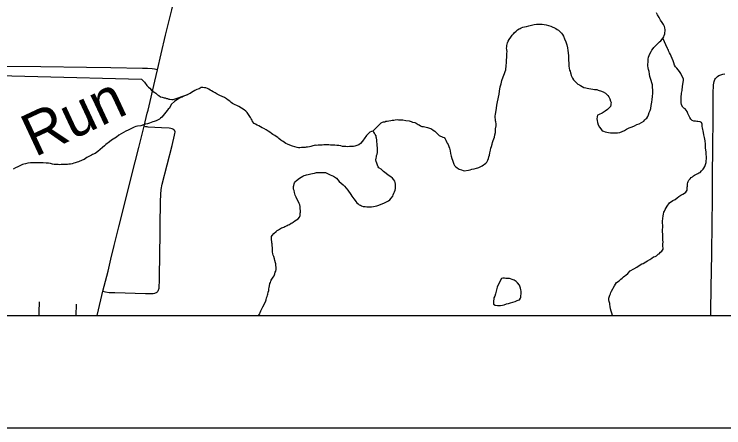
# Model space of a CAD drawing. Extents: x 2.1 to 73.9, y 4 to 26.
# Drawn here: x 43.39 to 44.021, y 18.005 to 18.373 of the extents above; entities that cross this region are included whole.
import ezdxf

# ---------------------------------------------------------------- set-up
doc = ezdxf.new("R2010")
doc.units = 0
for name, color, linetype in [('GM_X_City_Street', 7, 'Continuous'), ('GM_X_County_Road', 7, 'Continuous'), ('GM_X_Minor_Lake', 7, 'Continuous'), ('GM_X_Minor_Lake_Text', 7, 'Continuous'), ('GM_X_Minor_River', 7, 'Continuous'), ('GM_X_Township_Road', 7, 'Continuous'), ('SH_Data', 7, 'Continuous')]:
    doc.layers.add(name, color=color, linetype=linetype)

msp = doc.modelspace()

# ---------------------------------------------------------------- linework, layer by layer
at = {"layer": 'GM_X_City_Street'}
msp.add_line((43.44493, 18.10511), (43.44524, 18.11503), dxfattribs=at)
for points in [[(43.4688, 18.1266), (43.47103, 18.12599), (43.47421, 18.12555), (43.47923, 18.12547), (43.50655, 18.12466), (43.50867, 18.12459), (43.51332, 18.12468), (43.51486, 18.12486), (43.51566, 18.1251), (43.51632, 18.12542), (43.51689, 18.12584), (43.51743, 18.12647), (43.51783, 18.12703), (43.5182, 18.12781), (43.51844, 18.12849), (43.51864, 18.12929), (43.51883, 18.13083), (43.519, 18.13548), (43.51919, 18.14784), (43.51922, 18.15093), (43.5197, 18.18643), (43.51978, 18.19259), (43.51988, 18.19878), (43.52002, 18.20653), (43.52019, 18.21273), (43.52064, 18.21735), (43.52145, 18.22192), (43.5302, 18.25649), (43.53237, 18.26552), (43.53271, 18.26699), (43.53287, 18.26812), (43.5329, 18.26844), (43.53289, 18.26875), (43.53277, 18.26926), (43.5326, 18.2696), (43.53238, 18.26984), (43.53177, 18.27039), (43.53105, 18.27081), (43.53047, 18.27108), (43.52906, 18.27154), (43.52758, 18.2718), (43.52083, 18.27218), (43.50896, 18.27272), (43.50808, 18.27283), (43.50699, 18.27302), (43.50535, 18.27346)], [(43.41201, 18.10511), (43.41207, 18.108), (43.41237, 18.11723)]]:
    msp.add_lwpolyline(points, dxfattribs=at)
at = {"layer": 'GM_X_County_Road'}
for points in [[(43.51734, 18.32372), (43.52065, 18.33781), (43.52449, 18.35446), (43.52991, 18.37713), (43.53608, 18.40442), (43.5417, 18.42863), (43.54558, 18.44528), (43.54639, 18.44885)], [(43.50535, 18.27346), (43.50815, 18.28503), (43.50885, 18.2879), (43.51497, 18.3136), (43.51734, 18.32372)], [(44.01442, 18.31698), (44.01549, 18.31775), (44.01663, 18.31851), (44.01832, 18.31928), (44.0203, 18.31986), (44.02187, 18.3202)], [(44.00955, 18.10511), (44.00957, 18.1085), (44.00995, 18.13023), (44.01028, 18.15972), (44.01067, 18.18765), (44.01095, 18.20782), (44.01111, 18.228), (44.01143, 18.25594), (44.01162, 18.27922), (44.0117, 18.29318), (44.01173, 18.30406), (44.01182, 18.30879), (44.01197, 18.31048), (44.01251, 18.31346), (44.01319, 18.31507), (44.0138, 18.31607), (44.01442, 18.31698)], [(43.4688, 18.1266), (43.46988, 18.13108), (43.47331, 18.14463), (43.47588, 18.15519), (43.47887, 18.16725), (43.48297, 18.18385), (43.48712, 18.20042), (43.49427, 18.22907), (43.50069, 18.2547), (43.50535, 18.27346)], [(43.46367, 18.10511), (43.46695, 18.11901), (43.4688, 18.1266)]]:
    msp.add_lwpolyline(points, dxfattribs=at)
at = {"layer": 'GM_X_Minor_Lake'}
for points in [[(43.82344, 18.13806), (43.81971, 18.13126), (43.81931, 18.13032), (43.81887, 18.12786), (43.81804, 18.12446), (43.81723, 18.1222), (43.81663, 18.12089), (43.81641, 18.11956), (43.81618, 18.11805), (43.81613, 18.11596), (43.81611, 18.11501), (43.81781, 18.11421), (43.8197, 18.11398), (43.82122, 18.11394), (43.82256, 18.1141), (43.82408, 18.11426), (43.8258, 18.1146), (43.82772, 18.11531), (43.82963, 18.11584), (43.83135, 18.11637), (43.83537, 18.11761), (43.83729, 18.11832), (43.83825, 18.11868), (43.83921, 18.11904), (43.84019, 18.12035), (43.8404, 18.12148), (43.84063, 18.123), (43.84084, 18.12394), (43.84087, 18.12527), (43.84071, 18.12679), (43.84036, 18.12794), (43.8402, 18.12927), (43.84003, 18.13023), (43.83931, 18.13214), (43.83765, 18.13427), (43.83634, 18.13544), (43.83466, 18.13662), (43.83277, 18.13723), (43.83126, 18.13765), (43.83031, 18.13786), (43.82936, 18.13788), (43.82842, 18.13809), (43.82728, 18.13812), (43.82595, 18.13815), (43.82443, 18.13818), (43.82344, 18.13806)], [(43.82344, 18.13806), (43.81971, 18.13126), (43.81931, 18.13032), (43.81887, 18.12786), (43.81804, 18.12446), (43.81723, 18.1222), (43.81663, 18.12089), (43.81641, 18.11956), (43.81618, 18.11805), (43.81613, 18.11596), (43.81611, 18.11501), (43.81781, 18.11421), (43.8197, 18.11398), (43.82122, 18.11394), (43.82256, 18.1141), (43.82408, 18.11426), (43.8258, 18.1146), (43.82772, 18.11531), (43.82963, 18.11584), (43.83135, 18.11637), (43.83537, 18.11761), (43.83729, 18.11832), (43.83825, 18.11868)], [(43.83825, 18.11868), (43.83921, 18.11904), (43.84019, 18.12035), (43.8404, 18.12148), (43.84063, 18.123), (43.84084, 18.12394), (43.84087, 18.12527), (43.84071, 18.12679), (43.84036, 18.12794), (43.8402, 18.12927), (43.84003, 18.13023), (43.83931, 18.13214), (43.83765, 18.13427), (43.83634, 18.13544), (43.83466, 18.13662), (43.83277, 18.13723), (43.83126, 18.13765), (43.83031, 18.13786), (43.82936, 18.13788), (43.82842, 18.13809), (43.82728, 18.13812), (43.82595, 18.13815), (43.82443, 18.13818), (43.82344, 18.13806)]]:
    msp.add_lwpolyline(points, dxfattribs=at)
at = {"layer": 'GM_X_Minor_River'}
for points in [[(43.96733, 18.36399), (43.96624, 18.36591), (43.96476, 18.36803), (43.96348, 18.37034), (43.96202, 18.37266), (43.96111, 18.37457)], [(43.81807, 18.27831), (43.81791, 18.27945), (43.81776, 18.28117), (43.81779, 18.28287), (43.81801, 18.28401), (43.81824, 18.2859), (43.81847, 18.28761), (43.81871, 18.28969), (43.81914, 18.29215), (43.81979, 18.29536), (43.82127, 18.30198), (43.82152, 18.30482), (43.82218, 18.30861), (43.82299, 18.31125), (43.82363, 18.31427), (43.82485, 18.31747), (43.82586, 18.3203), (43.82666, 18.32218), (43.82708, 18.32369), (43.8273, 18.32501), (43.82752, 18.32634), (43.82755, 18.32786), (43.82778, 18.32975), (43.82783, 18.33165), (43.82785, 18.33279), (43.82808, 18.3343), (43.82811, 18.33582), (43.82814, 18.33734), (43.82817, 18.33848), (43.8282, 18.33962), (43.82805, 18.34171), (43.82789, 18.34304), (43.82792, 18.34418), (43.82813, 18.34532), (43.82835, 18.34664), (43.82876, 18.34758), (43.82917, 18.34909), (43.83016, 18.35078), (43.83153, 18.35284), (43.83271, 18.35452), (43.83388, 18.35563), (43.83466, 18.35675), (43.83622, 18.35824), (43.83757, 18.35916), (43.83892, 18.36007), (43.83989, 18.36062), (43.84085, 18.36117), (43.84219, 18.36171), (43.84372, 18.36205), (43.84544, 18.3624), (43.84754, 18.36292), (43.85002, 18.36343), (43.85232, 18.36395), (43.85442, 18.36428), (43.85708, 18.36441), (43.85936, 18.36436), (43.86126, 18.36412), (43.86296, 18.36371), (43.86523, 18.36327), (43.86711, 18.36247), (43.87163, 18.36047), (43.87294, 18.35968), (43.87388, 18.35909), (43.875, 18.35811), (43.87667, 18.35636), (43.8776, 18.3552), (43.87851, 18.35366), (43.87941, 18.35136), (43.88049, 18.34868), (43.88138, 18.346), (43.88189, 18.34333), (43.88241, 18.34085), (43.88274, 18.33875), (43.88287, 18.33628), (43.88301, 18.334), (43.88296, 18.33191), (43.88311, 18.33001), (43.88308, 18.32849), (43.88323, 18.32697), (43.88357, 18.32506), (43.88372, 18.32335), (43.88427, 18.32238), (43.88462, 18.32105), (43.88498, 18.32009), (43.88533, 18.31875), (43.88587, 18.31741), (43.8866, 18.31625), (43.88734, 18.31491), (43.88844, 18.31355), (43.88994, 18.31219), (43.89124, 18.31102), (43.89255, 18.31023), (43.89368, 18.30963), (43.89499, 18.30884), (43.8965, 18.30805), (43.89839, 18.30763), (43.89952, 18.30741), (43.90104, 18.307), (43.90274, 18.30677), (43.90464, 18.30653), (43.90615, 18.30631)], [(43.90615, 18.30631), (43.90729, 18.30628), (43.90824, 18.30607), (43.90918, 18.30567), (43.91032, 18.30545), (43.91145, 18.30505), (43.91371, 18.30424), (43.91596, 18.30286), (43.91801, 18.30091), (43.91893, 18.29956), (43.91965, 18.29783), (43.92018, 18.29592), (43.92072, 18.29477), (43.92069, 18.29344), (43.92067, 18.29249), (43.92026, 18.29117), (43.9189, 18.28968), (43.91754, 18.28839), (43.91541, 18.28691), (43.91271, 18.28527), (43.91021, 18.28399), (43.90868, 18.28346), (43.90826, 18.28176), (43.90823, 18.28024), (43.90838, 18.27853), (43.90872, 18.27681), (43.90925, 18.2749), (43.91034, 18.27278), (43.91163, 18.27105), (43.91293, 18.2695), (43.91406, 18.26909), (43.91538, 18.26849), (43.91689, 18.26827), (43.9186, 18.26785), (43.9203, 18.26762), (43.9222, 18.26758), (43.92429, 18.26753), (43.92639, 18.26767), (43.92867, 18.268), (43.93059, 18.26871), (43.9327, 18.26962), (43.93463, 18.2709), (43.93694, 18.27218), (43.93943, 18.27307), (43.94174, 18.27397), (43.94366, 18.27506), (43.94577, 18.27578), (43.94982, 18.27815), (43.95079, 18.27908), (43.95157, 18.2802), (43.95273, 18.28075), (43.95351, 18.28206), (43.95412, 18.28356), (43.95474, 18.28583), (43.95554, 18.28752), (43.95615, 18.2894), (43.95659, 18.29205), (43.95704, 18.29489), (43.95728, 18.29736), (43.95753, 18.30001), (43.95778, 18.30285), (43.95782, 18.30456), (43.95786, 18.30627), (43.95771, 18.30779), (43.95773, 18.30893), (43.95757, 18.31027), (43.95704, 18.31218), (43.95633, 18.31409), (43.9558, 18.316), (43.95527, 18.31773), (43.95493, 18.31982), (43.95461, 18.32211), (43.95408, 18.32402), (43.95373, 18.32555), (43.95358, 18.32726), (43.95362, 18.32878), (43.95365, 18.33049), (43.95368, 18.33182), (43.9539, 18.33314), (43.95414, 18.33504), (43.95474, 18.33654), (43.95534, 18.33805), (43.95634, 18.33993), (43.95713, 18.34124), (43.95811, 18.34254), (43.95889, 18.34366), (43.95987, 18.34478), (43.96084, 18.34571), (43.96259, 18.34757), (43.96376, 18.34868), (43.96492, 18.34961), (43.96628, 18.35109), (43.96766, 18.35315), (43.96807, 18.35428), (43.96848, 18.35579), (43.9687, 18.35693), (43.96892, 18.35825), (43.96875, 18.3594), (43.9686, 18.36111), (43.96825, 18.36226), (43.96733, 18.36399)], [(43.98886, 18.22237), (43.98908, 18.22351), (43.98948, 18.22445), (43.99008, 18.22557), (43.99124, 18.22669), (43.99203, 18.22781), (43.99318, 18.22854), (43.99415, 18.22928), (43.99512, 18.22983), (43.99627, 18.23056), (43.998, 18.23147), (43.99897, 18.23202), (43.99992, 18.23238), (44.00129, 18.23368), (44.00265, 18.23516), (44.00343, 18.23628), (44.00404, 18.23779), (44.00484, 18.23948), (44.00526, 18.24118), (44.00548, 18.2427), (44.00571, 18.2444), (44.00528, 18.25049), (44.00479, 18.2543), (44.00467, 18.25753), (44.00436, 18.26058), (44.00386, 18.26344), (44.00334, 18.26592), (44.003, 18.26782), (44.00266, 18.26935), (44.00231, 18.27069), (44.00215, 18.27202), (44.00179, 18.27317), (44.00182, 18.27431), (44.00184, 18.27545), (44.00111, 18.2768), (43.99999, 18.27739), (43.99809, 18.27762), (43.99696, 18.27784), (43.99582, 18.27787), (43.99449, 18.27809), (43.99298, 18.27869), (43.99168, 18.27986), (43.99095, 18.28121), (43.99003, 18.28294), (43.98913, 18.28486), (43.98841, 18.28658), (43.98749, 18.28793), (43.98656, 18.2889), (43.98562, 18.28968), (43.98469, 18.29046), (43.98341, 18.29258), (43.98307, 18.29449), (43.98311, 18.2962), (43.98316, 18.29829), (43.9832, 18.30019), (43.98342, 18.3017), (43.98345, 18.30303), (43.98367, 18.30416), (43.98388, 18.3053), (43.9841, 18.30662), (43.98432, 18.30795), (43.98435, 18.30909), (43.98457, 18.3106), (43.985, 18.31268), (43.98523, 18.3142), (43.98506, 18.31534), (43.9829, 18.32052), (43.98179, 18.32225), (43.9805, 18.3238), (43.9792, 18.32516), (43.97809, 18.32651), (43.97717, 18.32786), (43.97664, 18.32996), (43.97592, 18.33169), (43.97521, 18.3338), (43.9743, 18.33572), (43.97358, 18.33744), (43.97285, 18.33879), (43.97212, 18.33995), (43.97176, 18.34109), (43.97121, 18.34205), (43.97085, 18.34263), (43.96676, 18.3518)], [(43.01674, 18.33636), (43.31889, 18.33107), (43.31846, 18.32025), (43.50294, 18.31531)], [(43.50294, 18.31531), (43.50573, 18.31259), (43.50776, 18.3097), (43.50925, 18.30833), (43.51037, 18.30736), (43.51167, 18.306), (43.51353, 18.30444), (43.51484, 18.30346), (43.51578, 18.30287), (43.51727, 18.3015), (43.5184, 18.30091), (43.52008, 18.29973), (43.52141, 18.29951), (43.5231, 18.2989), (43.52424, 18.29869), (43.52537, 18.29828), (43.52632, 18.29807), (43.52745, 18.29766), (43.52839, 18.29745), (43.52991, 18.29742), (43.53124, 18.29739), (43.54427, 18.30165)], [(43.69476, 18.25624), (43.69285, 18.25572), (43.69152, 18.25556), (43.6898, 18.25541), (43.68809, 18.25545), (43.68638, 18.2553), (43.68486, 18.25533), (43.68296, 18.25537), (43.68182, 18.25559), (43.68031, 18.256), (43.6786, 18.25623), (43.6769, 18.25646), (43.675, 18.2567), (43.6731, 18.25674), (43.6712, 18.25678), (43.66968, 18.25682), (43.66835, 18.25685), (43.6674, 18.25687), (43.66645, 18.25689), (43.66531, 18.25692), (43.66379, 18.25676), (43.66189, 18.2568), (43.66017, 18.25665), (43.65846, 18.2565), (43.65751, 18.25652), (43.65655, 18.25636), (43.6556, 18.256), (43.65368, 18.25547), (43.65253, 18.25512), (43.65082, 18.25497), (43.64968, 18.2548), (43.64853, 18.25464), (43.64701, 18.25448), (43.64549, 18.25452), (43.64396, 18.25436), (43.64263, 18.25439), (43.6415, 18.25461), (43.63734, 18.25585), (43.63489, 18.25666), (43.63301, 18.25746), (43.6315, 18.25826), (43.63019, 18.25905), (43.62907, 18.25983), (43.62794, 18.26043), (43.627, 18.26102), (43.62514, 18.26258), (43.6242, 18.26336), (43.62289, 18.26434), (43.62159, 18.26532), (43.61989, 18.26612), (43.61877, 18.2669), (43.61728, 18.26808), (43.61559, 18.26926), (43.61391, 18.27043), (43.61203, 18.27143), (43.61033, 18.27223), (43.60883, 18.27302), (43.60733, 18.27381), (43.60582, 18.27442), (43.60451, 18.27521), (43.60319, 18.276), (43.6019, 18.27773), (43.60136, 18.27889), (43.60063, 18.28023), (43.59989, 18.2812), (43.59934, 18.28216), (43.59824, 18.2839), (43.59714, 18.28582), (43.59584, 18.28699), (43.59453, 18.28797), (43.58966, 18.29112), (43.58796, 18.29192), (43.58646, 18.29252), (43.58533, 18.29312), (43.58401, 18.29372), (43.5827, 18.29451), (43.58158, 18.29567), (43.58009, 18.29684), (43.57859, 18.29783), (43.57691, 18.29901), (43.57484, 18.3), (43.57277, 18.301), (43.57051, 18.30219), (43.56864, 18.30318), (43.56695, 18.30417), (43.56544, 18.30496), (43.56413, 18.30575), (43.56301, 18.30654), (43.56169, 18.30695), (43.56037, 18.30755), (43.55923, 18.30777), (43.55753, 18.30799), (43.556, 18.30784), (43.55427, 18.30693), (43.55216, 18.30622), (43.55062, 18.3053), (43.54908, 18.30439), (43.54754, 18.30347), (43.54638, 18.30274), (43.54542, 18.30238), (43.54427, 18.30165)], [(43.54427, 18.30165), (43.54273, 18.30111), (43.54023, 18.29984), (43.53909, 18.29949), (43.53793, 18.29894), (43.53697, 18.29859), (43.53523, 18.2973), (43.53369, 18.29638), (43.53234, 18.29546), (43.52982, 18.29305), (43.52863, 18.29099), (43.52784, 18.28968), (43.52686, 18.28856), (43.52589, 18.28744), (43.52472, 18.28614), (43.52354, 18.28446), (43.52236, 18.28296), (43.52119, 18.28166), (43.52003, 18.28055), (43.51906, 18.27981), (43.51791, 18.27908), (43.51618, 18.27836), (43.51445, 18.27764), (43.51311, 18.27729), (43.51158, 18.27675), (43.51005, 18.27622), (43.50832, 18.27569), (43.5066, 18.27534), (43.50469, 18.27482), (43.50239, 18.27392), (43.49953, 18.27361), (43.498, 18.27326), (43.49647, 18.27254), (43.49474, 18.27182), (43.49301, 18.27091), (43.49109, 18.27), (43.48916, 18.26909), (43.48704, 18.26781), (43.48493, 18.26672), (43.483, 18.26544), (43.48087, 18.26377), (43.47779, 18.26195), (43.47644, 18.26122), (43.4747, 18.25974), (43.47353, 18.25881), (43.47257, 18.25807), (43.47141, 18.25734), (43.47024, 18.25604), (43.4685, 18.25456), (43.46636, 18.25271), (43.46423, 18.25105), (43.46191, 18.2492), (43.45961, 18.2483), (43.45846, 18.24776), (43.45442, 18.24557), (43.45325, 18.24465), (43.45191, 18.24392), (43.45037, 18.24338), (43.44922, 18.24284), (43.44807, 18.2423), (43.44711, 18.24194), (43.44577, 18.2414), (43.44405, 18.24106), (43.4429, 18.24052), (43.44137, 18.24017), (43.43984, 18.23982), (43.4385, 18.23966), (43.43736, 18.2395), (43.43641, 18.23952), (43.43546, 18.23954), (43.43432, 18.23938), (43.4328, 18.23941), (43.43147, 18.23945), (43.43013, 18.23928), (43.4288, 18.23932), (43.42785, 18.23934), (43.42671, 18.23936), (43.42539, 18.23958), (43.42387, 18.23981), (43.42217, 18.24042), (43.42028, 18.24065), (43.41819, 18.2407), (43.41572, 18.24094), (43.41401, 18.24079), (43.4123, 18.24083), (43.41078, 18.24086), (43.40925, 18.2409), (43.40698, 18.24095), (43.40431, 18.24082), (43.40183, 18.2405), (43.39992, 18.24016), (43.39839, 18.23981), (43.39725, 18.23946), (43.39551, 18.23855), (43.39302, 18.23747), (43.3909, 18.23638), (43.38879, 18.23528)], [(43.70877, 18.269), (43.71613, 18.27646), (43.71747, 18.277), (43.71843, 18.27736), (43.71939, 18.27752), (43.72054, 18.27788), (43.72168, 18.27804), (43.72302, 18.27839), (43.72493, 18.27873), (43.72607, 18.27889), (43.72741, 18.27905), (43.72874, 18.27921), (43.73046, 18.27936), (43.73178, 18.27933), (43.7333, 18.27911), (43.73539, 18.27906), (43.73823, 18.27861), (43.74107, 18.27817), (43.74297, 18.27775), (43.74428, 18.27714), (43.74617, 18.27672), (43.74731, 18.27632), (43.74824, 18.27573), (43.74918, 18.27513), (43.75012, 18.27473), (43.75125, 18.27395), (43.75256, 18.27335), (43.75389, 18.27313), (43.75749, 18.27248), (43.75918, 18.27187), (43.76012, 18.27146), (43.76107, 18.27106), (43.76238, 18.27009), (43.76387, 18.2691), (43.765, 18.26832), (43.76648, 18.26676), (43.76778, 18.26521), (43.76891, 18.26481), (43.76985, 18.26441), (43.77117, 18.26381), (43.7723, 18.2634), (43.77323, 18.26243), (43.77377, 18.26109), (43.7745, 18.25955), (43.77504, 18.2584), (43.77577, 18.25724), (43.77613, 18.25628), (43.77649, 18.25533), (43.77703, 18.25399), (43.77739, 18.25284), (43.77774, 18.2515), (43.77807, 18.24921), (43.77858, 18.24673), (43.77911, 18.24482), (43.77964, 18.24329), (43.78, 18.24233), (43.78053, 18.24061), (43.78089, 18.23965), (43.78163, 18.23869), (43.78274, 18.23733), (43.78386, 18.23636), (43.78574, 18.23536), (43.78762, 18.23456), (43.78913, 18.23415), (43.79008, 18.23393), (43.79408, 18.23441), (43.79542, 18.23476), (43.79695, 18.2353), (43.79886, 18.23563), (43.80097, 18.23615), (43.8023, 18.2365), (43.80326, 18.23686), (43.80442, 18.23741), (43.80596, 18.23832), (43.8073, 18.23905), (43.80827, 18.2396), (43.80924, 18.24052), (43.81021, 18.24145), (43.81101, 18.24333), (43.81161, 18.24465), (43.81203, 18.24635), (43.81264, 18.24785), (43.81306, 18.24993), (43.81349, 18.2522), (43.81392, 18.25409), (43.81433, 18.2556), (43.81494, 18.25749), (43.81536, 18.259), (43.81597, 18.26069), (43.81657, 18.2622), (43.81699, 18.2639), (43.81742, 18.26598), (43.81784, 18.26806), (43.8181, 18.27109), (43.81854, 18.27374), (43.81858, 18.27564), (43.81824, 18.27736), (43.81807, 18.27831)], [(43.65695, 18.23185), (43.65867, 18.23219), (43.66058, 18.23233), (43.66229, 18.23229), (43.664, 18.23245), (43.66552, 18.23241), (43.66685, 18.23219), (43.66779, 18.23179), (43.6691, 18.231), (43.6708, 18.2302), (43.6723, 18.2296), (43.67381, 18.22899), (43.67475, 18.22859), (43.67643, 18.22722), (43.67773, 18.22586), (43.67903, 18.22431), (43.6807, 18.22276), (43.68238, 18.22139), (43.6835, 18.22022), (43.68517, 18.21829), (43.68646, 18.21674), (43.68941, 18.21268), (43.69014, 18.21134), (43.69106, 18.20999), (43.69199, 18.20882), (43.6931, 18.20747), (43.69384, 18.2065), (43.69476, 18.20534), (43.69588, 18.20456), (43.69681, 18.20359), (43.69775, 18.20318), (43.69889, 18.20278), (43.70039, 18.20218), (43.70191, 18.20195), (43.70361, 18.20172), (43.70495, 18.20188), (43.70628, 18.20185), (43.7078, 18.20182), (43.70933, 18.20216), (43.71104, 18.20231), (43.71238, 18.20266), (43.71429, 18.20319), (43.71622, 18.20409), (43.71852, 18.20518), (43.72044, 18.2059), (43.72159, 18.20644), (43.72274, 18.20698), (43.7241, 18.2079), (43.72508, 18.2094), (43.72664, 18.21126), (43.72705, 18.21258), (43.72765, 18.2139), (43.72806, 18.21503), (43.72867, 18.21672), (43.72889, 18.21805), (43.72891, 18.219), (43.72893, 18.22014), (43.72897, 18.22184), (43.72882, 18.22337), (43.72846, 18.22452), (43.72754, 18.22587), (43.72625, 18.22742), (43.72494, 18.22839), (43.72325, 18.22938), (43.7182, 18.23311), (43.71635, 18.23524), (43.71428, 18.23643), (43.71354, 18.23739), (43.71301, 18.23892), (43.71228, 18.24065), (43.71174, 18.24199), (43.71159, 18.24351), (43.71181, 18.24503), (43.71203, 18.24635), (43.71225, 18.24749), (43.71265, 18.24862), (43.71307, 18.25013), (43.71309, 18.25108), (43.71312, 18.25241), (43.71298, 18.2545), (43.71282, 18.25621), (43.71267, 18.25773), (43.71252, 18.25964), (43.71237, 18.26154), (43.71202, 18.26288), (43.71186, 18.26383), (43.71169, 18.26497), (43.71096, 18.26613), (43.71041, 18.26728), (43.70967, 18.26825), (43.70874, 18.26903), (43.7076, 18.26887), (43.70625, 18.26814), (43.70489, 18.26703), (43.70333, 18.26517), (43.70118, 18.26237), (43.70039, 18.26124), (43.6996, 18.26012), (43.69785, 18.25826), (43.6963, 18.25697), (43.69476, 18.25624)], [(43.60933, 18.1091), (43.61013, 18.11098), (43.61112, 18.11267), (43.61332, 18.11736), (43.61392, 18.11887), (43.61434, 18.12076), (43.61475, 18.12208), (43.61516, 18.12302), (43.61537, 18.12396), (43.61579, 18.12586), (43.6162, 18.12737), (43.61642, 18.12869), (43.61664, 18.13001), (43.61686, 18.13134), (43.61729, 18.13342), (43.6177, 18.13455), (43.6181, 18.13549), (43.6185, 18.13662), (43.61968, 18.1383), (43.62027, 18.13924), (43.62106, 18.14036), (43.62167, 18.14205), (43.62208, 18.14357), (43.62248, 18.1445), (43.62271, 18.14602), (43.62273, 18.14697), (43.62275, 18.14811), (43.62259, 18.14944), (43.62244, 18.15096), (43.62227, 18.15192), (43.62175, 18.15402), (43.6214, 18.15555), (43.62069, 18.15765), (43.62014, 18.1588), (43.61979, 18.15995), (43.61964, 18.16166), (43.61948, 18.16319), (43.61951, 18.16452), (43.61953, 18.16565), (43.61938, 18.16718), (43.61922, 18.1687), (43.61905, 18.16965), (43.61889, 18.17099), (43.61874, 18.17251), (43.61878, 18.17441), (43.6188, 18.17536), (43.61939, 18.17629), (43.62076, 18.17797), (43.62271, 18.17983), (43.62387, 18.18075), (43.62483, 18.1813), (43.62657, 18.1824), (43.62753, 18.18295), (43.62868, 18.1833), (43.62964, 18.18366), (43.6306, 18.18421), (43.63156, 18.18456), (43.63271, 18.18511), (43.63367, 18.18566), (43.63463, 18.18601), (43.63618, 18.18712), (43.63714, 18.18766), (43.6381, 18.18821), (43.63946, 18.18932), (43.641, 18.19024), (43.64235, 18.19115), (43.64352, 18.19246), (43.64413, 18.19415), (43.64417, 18.19605), (43.64438, 18.197), (43.64441, 18.19832), (43.64427, 18.20042), (43.64411, 18.20194), (43.64377, 18.20347), (43.64322, 18.20462), (43.64287, 18.20558), (43.64123, 18.20903), (43.64069, 18.21038), (43.63978, 18.21211), (43.63943, 18.21325), (43.63908, 18.21459), (43.63873, 18.21631), (43.63838, 18.21746), (43.63821, 18.21841), (43.63824, 18.21974), (43.63846, 18.22087), (43.63887, 18.22219), (43.63927, 18.22313), (43.63986, 18.22407), (43.64064, 18.225), (43.64257, 18.22648), (43.64374, 18.2274), (43.64509, 18.22832), (43.64663, 18.22904), (43.64778, 18.22959), (43.64893, 18.22994), (43.64988, 18.23011), (43.65141, 18.23045), (43.65371, 18.23116), (43.65524, 18.23151), (43.65695, 18.23185)], [(43.92194, 18.10511), (43.92145, 18.10709), (43.92073, 18.10901), (43.9202, 18.11092), (43.91987, 18.11302), (43.91972, 18.11473), (43.91955, 18.11587), (43.91921, 18.1174), (43.91886, 18.11893), (43.9189, 18.12064), (43.91932, 18.12234), (43.91972, 18.12328), (43.92012, 18.12441), (43.92053, 18.12554), (43.92112, 18.12667), (43.9237, 18.13136), (43.92548, 18.13435), (43.92799, 18.13601), (43.92935, 18.1373), (43.93051, 18.13823), (43.93187, 18.13934), (43.93303, 18.14026), (43.93399, 18.141), (43.93555, 18.14248), (43.93788, 18.14471), (43.94097, 18.14673), (43.94366, 18.14799), (43.94578, 18.14947), (43.9481, 18.15093), (43.94944, 18.15147), (43.95156, 18.15294), (43.9533, 18.15385), (43.95522, 18.15495), (43.95696, 18.15605), (43.9585, 18.15715), (43.96003, 18.15769), (43.96119, 18.15823), (43.96255, 18.15953), (43.96351, 18.16008), (43.96487, 18.16138), (43.96584, 18.1623), (43.96702, 18.16399), (43.96705, 18.16532), (43.96689, 18.16646), (43.96691, 18.16741), (43.96694, 18.16874), (43.96697, 18.17026), (43.96683, 18.17235), (43.96669, 18.17482), (43.96675, 18.17729), (43.96661, 18.17976), (43.96665, 18.18147), (43.96669, 18.18337), (43.96674, 18.18546), (43.96659, 18.18717), (43.96663, 18.18907), (43.96712, 18.1938), (43.96753, 18.19531), (43.96776, 18.19702), (43.96816, 18.19796), (43.96896, 18.19946), (43.96975, 18.20077), (43.97074, 18.20246), (43.97289, 18.20526), (43.97579, 18.20747), (43.97771, 18.20838), (43.97965, 18.20986), (43.98119, 18.21096), (43.98293, 18.21206), (43.98466, 18.21316), (43.98621, 18.21407), (43.98717, 18.21481), (43.98836, 18.21668), (43.98857, 18.21763), (43.9886, 18.21915), (43.98882, 18.22028), (43.98884, 18.22123), (43.98886, 18.22237)], [(43.60712, 18.10511), (43.60715, 18.10516), (43.60832, 18.10665), (43.60873, 18.10759), (43.60933, 18.1091)]]:
    msp.add_lwpolyline(points, dxfattribs=at)
at = {"layer": 'GM_X_Township_Road'}
msp.add_lwpolyline([(43.32431, 18.32764), (43.35582, 18.32749), (43.38233, 18.32708), (43.41353, 18.32678), (43.45408, 18.3262), (43.47591, 18.32579), (43.50398, 18.32523), (43.50839, 18.32508), (43.51245, 18.32495), (43.5145, 18.32464), (43.51585, 18.32426), (43.51734, 18.32372)], dxfattribs=at)
at = {"layer": 'SH_Data'}
for p, q in [((41.95853, 18.10511), (48.75853, 18.10511)), ((41.85853, 18.00511), (48.85853, 18.00511))]:
    msp.add_line(p, q, dxfattribs=at)

# ---------------------------------------------------------------- texts
at = {"layer": 'GM_X_Minor_Lake_Text'}
msp.add_text('Run', height=0.037893, rotation=25.04016, dxfattribs=at).set_placement((43.40815, 18.24577))

doc.saveas('drawing.dxf')
